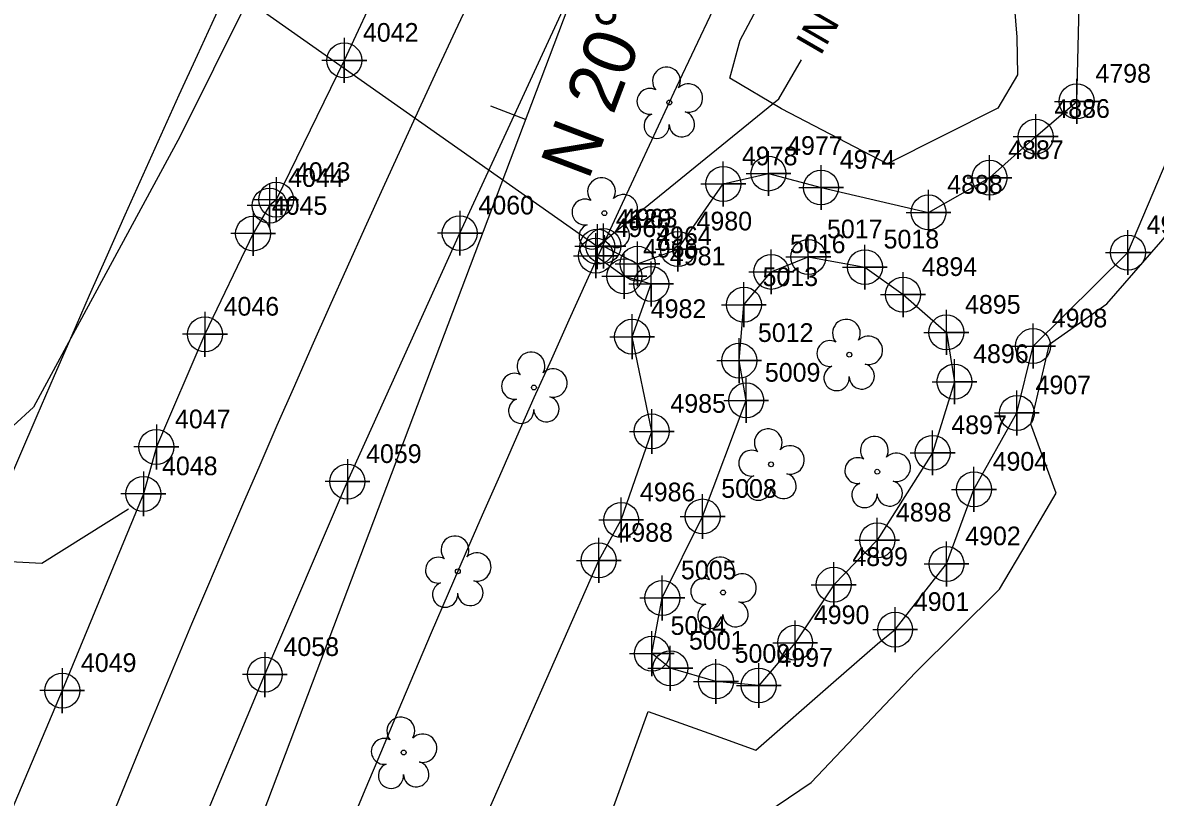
# Model space of a CAD drawing. Extents: x 1653123 to 1656194, y 596584 to 600233.
# Drawn here: x 1653582.5 to 1653734.2, y 597710.9 to 597814.6 of the extents above; entities that cross this region are included whole.
import ezdxf

# ---------------------------------------------------------------- set-up
doc = ezdxf.new("R2010")
doc.units = 0
for name, color, linetype in [('Exist Horizontal Alignment', 7, 'Continuous'), ('Exist Horizontal Baseline Alignment', 7, 'Continuous'), ('Exist Horizontal Baseline Alignment Direction Label', 7, 'Continuous'), ('Exist Horizontal Baseline Alignment Tick small', 7, 'Continuous'), ('Exist Hydro Jurisdictional Stream or Body of Water', 7, 'Continuous'), ('Exist Hydro Stream or Body of Water Cogo Number', 7, 'Continuous'), ('Exist Right of Way Line', 7, 'Continuous'), ('Exist Roads EOP Cogo Point CELL', 7, 'Continuous'), ('Exist Structure Minor Pipes RCP 30 Inch', 7, 'Continuous'), ('Exist Structure Minor Pipes RCP 30 Inch Cogo Number', 7, 'Continuous'), ('Exist Structure Minor Pipes RCP 30 Inch Cogo Point CELL', 7, 'Continuous'), ('Exist Structure Minor Pipes RCP 30 Inch Invert', 7, 'Continuous'), ('Exist Vegetation Tree CELL', 7, 'Continuous'), ('Exist Vegetation Woods Line', 7, 'Continuous'), ('Prop Conc Shoulder Berm Gutter', 7, 'Continuous'), ('Prop Easement Construction', 7, 'Continuous'), ('Prop Easement Construction Station Offsets', 7, 'Continuous'), ('Prop Guardrail Anchor Unit CELL', 7, 'Continuous'), ('Prop Horizontal Alignment', 7, 'Continuous')]:
    doc.layers.add(name, color=color, linetype=linetype)

msp = doc.modelspace()

# ---------------------------------------------------------------- linework, layer by layer
at = {"layer": 'Exist Horizontal Alignment'}
msp.add_arc((1655696.35, 596851.16), 2270, 149.9451, 159.30371, dxfattribs=at)
at = {"layer": 'Exist Horizontal Baseline Alignment'}
msp.add_line((1653570.02, 597590.97), (1653732.12, 598018.79), dxfattribs=at)
at = {"layer": 'Exist Horizontal Baseline Alignment Tick small'}
msp.add_line((1653649.85, 597801.66), (1653645.18, 597803.44), dxfattribs=at)
at = {"layer": 'Exist Hydro Jurisdictional Stream or Body of Water'}
for points in [[(1653703.81, 597789.23), (1653711.98, 597793.87), (1653718.16, 597799.38), (1653723.66, 597804.09), (1653724.22, 597826.08), (1653730.43, 597843.27), (1653737.9, 597848.38), (1653749, 597867.92), (1653762.46, 597888.24), (1653771.7, 597908), (1653776.11, 597927.83), (1653775.18, 597952.39), (1653772.63, 597974.68), (1653768.36, 597994.45), (1653761.04, 598003.47), (1653757.33, 598006.27), (1653756.65, 598007.49)], [(1653717.81, 597771.34), (1653730.52, 597783.85), (1653737.92, 597801.32)], [(1653670.24, 597784.32), (1653676.32, 597793.03), (1653682.37, 597794.43), (1653689.42, 597792.56), (1653703.81, 597789.23)], [(1653659.44, 597784.65), (1653659.25, 597783.43), (1653663.06, 597780.68), (1653666.67, 597779.65)], [(1653659.44, 597784.65), (1653660.26, 597784.72), (1653664.84, 597782.35), (1653670.24, 597784.32)], [(1653666.76, 597730.18), (1653668.15, 597737.62), (1653673.55, 597748.53), (1653679.39, 597764.07), (1653678.46, 597769.39), (1653679.08, 597776.87), (1653682.75, 597781.27), (1653687.71, 597783.27), (1653695.29, 597781.9), (1653700.39, 597778.22), (1653706.2, 597773.17)], [(1653638.42, 597694.46), (1653659.64, 597742.65), (1653662.65, 597748.06), (1653666.74, 597759.91), (1653664.11, 597772.59), (1653666.67, 597779.65)], [(1653693.8, 597570.3), (1653681.46, 597588.06), (1653671.05, 597605.1), (1653663.13, 597623.2), (1653653.04, 597647.87), (1653652.69, 597665.53), (1653656.24, 597688.24), (1653658.32, 597700.51), (1653666.26, 597722.43)]]:
    msp.add_lwpolyline(points, dxfattribs=at)
at = {"layer": 'Exist Right of Way Line'}
for radius in [2300, 2240]:
    msp.add_arc((1655696.35, 596851.16), radius, 149.9451, 159.30371, dxfattribs=at)
at = {"layer": 'Exist Roads EOP Cogo Point CELL'}
for points in [[(1653625.56, 597812.57), (1653625.56, 597806.57), (1653625.56, 597809.57), (1653628.56, 597809.57), (1653622.56, 597809.57)], [(1653615.55, 597793.14), (1653615.55, 597787.14), (1653615.55, 597790.14), (1653618.55, 597790.14), (1653612.55, 597790.14)], [(1653616.44, 597793.93), (1653616.44, 597787.93), (1653616.44, 597790.93), (1653619.44, 597790.93), (1653613.44, 597790.93)], [(1653613.35, 597789.4), (1653613.35, 597783.4), (1653613.35, 597786.4), (1653616.35, 597786.4), (1653610.35, 597786.4)], [(1653641.03, 597789.45), (1653641.03, 597783.45), (1653641.03, 597786.45), (1653644.03, 597786.45), (1653638.03, 597786.45)], [(1653606.9, 597775.91), (1653606.9, 597769.91), (1653606.9, 597772.91), (1653609.9, 597772.91), (1653603.9, 597772.91)], [(1653600.39, 597760.83), (1653600.39, 597754.83), (1653600.39, 597757.83), (1653603.39, 597757.83), (1653597.39, 597757.83)], [(1653625.98, 597756.19), (1653625.98, 597750.19), (1653625.98, 597753.19), (1653628.98, 597753.19), (1653622.98, 597753.19)], [(1653598.65, 597754.55), (1653598.65, 597748.55), (1653598.65, 597751.55), (1653601.65, 597751.55), (1653595.65, 597751.55)], [(1653614.92, 597730.36), (1653614.92, 597724.36), (1653614.92, 597727.36), (1653617.92, 597727.36), (1653611.92, 597727.36)], [(1653587.79, 597728.22), (1653587.79, 597722.22), (1653587.79, 597725.22), (1653590.79, 597725.22), (1653584.79, 597725.22)]]:
    msp.add_lwpolyline(points, dxfattribs=at)
for centre in [(1653625.56, 597809.57), (1653616.44, 597790.93), (1653615.55, 597790.14), (1653613.35, 597786.4), (1653641.03, 597786.45), (1653606.9, 597772.91), (1653600.39, 597757.83), (1653625.98, 597753.19), (1653598.65, 597751.55), (1653614.92, 597727.36), (1653587.79, 597725.22)]:
    msp.add_circle(centre, 2.34, dxfattribs=at)
at = {"layer": 'Exist Structure Minor Pipes RCP 30 Inch'}
msp.add_line((1653659.44, 597784.65), (1653609.16, 597820.02), dxfattribs=at)
at = {"layer": 'Exist Structure Minor Pipes RCP 30 Inch Cogo Point CELL'}
msp.add_lwpolyline([(1653659.44, 597787.65), (1653659.44, 597781.65), (1653659.44, 597784.65), (1653662.44, 597784.65), (1653656.44, 597784.65)], dxfattribs=at)
msp.add_circle((1653659.44, 597784.65), 2.34, dxfattribs=at)
at = {"layer": 'Exist Structure Minor Pipes RCP 30 Inch Invert'}
msp.add_lwpolyline([(1653659.44, 597784.65), (1653683.77, 597804.44), (1653686.78, 597809.63)], dxfattribs=at)
at = {"layer": 'Exist Vegetation Tree CELL'}
for p, q in [((1653669.1, 597803.94), (1653669.1, 597803.94)), ((1653660.4, 597789.12), (1653660.4, 597789.12)), ((1653693.2, 597770.18), (1653693.2, 597770.18)), ((1653650.96, 597765.8), (1653650.96, 597765.8)), ((1653682.72, 597755.51), (1653682.72, 597755.51)), ((1653696.94, 597754.52), (1653696.94, 597754.52)), ((1653640.77, 597741.19), (1653640.77, 597741.19)), ((1653676.29, 597738.36), (1653676.29, 597738.36)), ((1653633.51, 597716.94), (1653633.51, 597716.94))]:
    msp.add_line(p, q, dxfattribs=at)
for centre in [(1653669.1, 597803.94), (1653660.4, 597789.12), (1653693.2, 597770.18), (1653650.96, 597765.8), (1653682.72, 597755.51), (1653696.94, 597754.52), (1653640.77, 597741.19), (1653676.29, 597738.36), (1653633.51, 597716.94)]:
    msp.add_circle(centre, 0.326, dxfattribs=at)
for centre, radius, start, end in [((1653668.71, 597806.81), 1.86, 330.1651, 219.7134), ((1653666.49, 597804.09), 1.73, 62.6636, 279.3457), ((1653671.65, 597804.53), 1.9, 257.1011, 134.1999), ((1653667.39, 597800.82), 1.69, 111.5671, 6.231), ((1653670.77, 597801.04), 1.7, 181.2822, 74.56), ((1653660.01, 597792), 1.86, 330.1651, 219.7134), ((1653662.95, 597789.71), 1.9, 257.1011, 134.1999), ((1653657.79, 597789.28), 1.73, 62.6636, 279.3457), ((1653658.69, 597786), 1.69, 111.5671, 6.231), ((1653662.07, 597786.23), 1.7, 181.2822, 74.56), ((1653692.81, 597773.06), 1.86, 330.1651, 219.7134), ((1653690.59, 597770.34), 1.73, 62.6636, 279.3457), ((1653695.75, 597770.77), 1.9, 257.1011, 134.1999), ((1653650.57, 597768.68), 1.86, 330.1651, 219.7134), ((1653694.87, 597767.28), 1.7, 181.2822, 74.56), ((1653648.35, 597765.96), 1.73, 62.6636, 279.3457), ((1653653.51, 597766.39), 1.9, 257.1011, 134.1999), ((1653691.49, 597767.06), 1.69, 111.5671, 6.231), ((1653649.25, 597762.68), 1.69, 111.5671, 6.231), ((1653652.63, 597762.9), 1.7, 181.2822, 74.56), ((1653682.34, 597758.39), 1.86, 330.1651, 219.7134), ((1653696.55, 597757.39), 1.86, 330.1651, 219.7134), ((1653680.12, 597755.67), 1.73, 62.6636, 279.3457), ((1653685.27, 597756.1), 1.9, 257.1011, 134.1999), ((1653699.49, 597755.11), 1.9, 257.1011, 134.1999), ((1653694.33, 597754.67), 1.73, 62.6636, 279.3457), ((1653681.02, 597752.39), 1.69, 111.5671, 6.231), ((1653684.39, 597752.62), 1.7, 181.2822, 74.56), ((1653695.23, 597751.4), 1.69, 111.5671, 6.231), ((1653698.61, 597751.62), 1.7, 181.2822, 74.56), ((1653640.39, 597744.06), 1.86, 330.1651, 219.7134), ((1653638.17, 597741.34), 1.73, 62.6636, 279.3457), ((1653643.32, 597741.77), 1.9, 257.1011, 134.1999), ((1653675.91, 597741.23), 1.86, 330.1651, 219.7134), ((1653673.69, 597738.51), 1.73, 62.6636, 279.3457), ((1653678.84, 597738.95), 1.9, 257.1011, 134.1999), ((1653639.07, 597738.07), 1.69, 111.5671, 6.231), ((1653642.44, 597738.29), 1.7, 181.2822, 74.56), ((1653677.96, 597735.46), 1.7, 181.2822, 74.56), ((1653674.59, 597735.24), 1.69, 111.5671, 6.231), ((1653633.13, 597719.81), 1.86, 330.1651, 219.7134), ((1653630.91, 597717.09), 1.73, 62.6636, 279.3457), ((1653636.06, 597717.52), 1.9, 257.1011, 134.1999), ((1653631.81, 597713.82), 1.69, 111.5671, 6.231), ((1653635.19, 597714.04), 1.7, 181.2822, 74.56)]:
    msp.add_arc(centre, radius, start, end, dxfattribs=at)
at = {"layer": 'Exist Vegetation Woods Line'}
for points in [[(1653661.33, 597915.51), (1653603.59, 597799.41), (1653583.95, 597763.16), (1653578.44, 597758.17), (1653564.7, 597761.25), (1653536.01, 597770.5), (1653508.63, 597776.57), (1653484.83, 597779.68), (1653482.87, 597781.33), (1653483.43, 597790.56), (1653492.03, 597811.3), (1653503.66, 597836.47), (1653511.56, 597849.92), (1653513.67, 597858.14), (1653513.6, 597868.54), (1653511.35, 597878.91), (1653507.78, 597891.42), (1653504.66, 597919.45), (1653504.85, 597944.49), (1653506.49, 597968.64), (1653509.77, 597999.99)], [(1653743.53, 597872.59), (1653727.72, 597849.07), (1653722.44, 597840.57), (1653717.66, 597833.58), (1653714.51, 597826.4), (1653715.63, 597812.68), (1653715.73, 597807.63), (1653713.11, 597803.16), (1653698.27, 597795.72), (1653684.13, 597803.11), (1653677.18, 597807.18), (1653678.58, 597812.27), (1653717.51, 597885.35)], [(1653682.04, 597708.83), (1653688.1, 597712.91), (1653702.08, 597727.65), (1653713.33, 597738.79), (1653717.03, 597745.05), (1653720.88, 597751.65), (1653717.53, 597760.89), (1653720.03, 597771.59), (1653727.67, 597777.01), (1653736.11, 597786.67), (1653742.22, 597795.29), (1653745.11, 597800.08), (1653748.1, 597805.18), (1653747.38, 597813.21), (1653742.97, 597818.93), (1653743.36, 597824.69), (1653753.29, 597833.05), (1653760.6, 597841.3), (1653772.69, 597855.66)]]:
    msp.add_lwpolyline(points, dxfattribs=at)
at = {"layer": 'Prop Conc Shoulder Berm Gutter'}
for points in [[(1653736.93, 598020.21), (1653736.61, 598019), (1653719.2, 597989.18), (1653700.61, 597956.07), (1653684.64, 597926.74), (1653670.3, 597899.63), (1653655.34, 597870.98), (1653640.41, 597841.45), (1653625.56, 597809.57), (1653616.44, 597790.93), (1653615.55, 597790.14), (1653613.35, 597786.4), (1653606.9, 597772.91), (1653600.39, 597757.83), (1653598.65, 597751.55), (1653587.79, 597725.22), (1653577.73, 597701.58), (1653574.75, 597692.21), (1653558.96, 597651.01), (1653542.08, 597605.71)], [(1653564.52, 597597.65), (1653581.19, 597642.12), (1653595.32, 597679.04), (1653605.24, 597704.17), (1653614.92, 597727.36), (1653625.98, 597753.19), (1653641.03, 597786.45), (1653655.92, 597818.68), (1653671.74, 597850.93), (1653688.35, 597883.45), (1653707.13, 597918.97), (1653720.66, 597943.73), (1653734.86, 597970.07), (1653749.84, 597996.36), (1653750.81, 597997.29)]]:
    msp.add_lwpolyline(points, dxfattribs=at)
at = {"layer": 'Prop Easement Construction'}
msp.add_lwpolyline([(1653468.85, 597775.82), (1653471.26, 597768.82), (1653474.67, 597765.31), (1653499.27, 597762.1), (1653508.84, 597760.94), (1653515.47, 597759.8), (1653528.77, 597757.03), (1653546.84, 597752.13), (1653557.14, 597748.35), (1653573.98, 597742.86), (1653585.04, 597742.26), (1653596.67, 597749.54)], dxfattribs=at)
at = {"layer": 'Prop Easement Construction Station Offsets'}
for points in [[(1653706.2, 597773.17), (1653707.28, 597766.57), (1653704.36, 597757.05), (1653696.94, 597745.35), (1653691.11, 597739.4), (1653685.95, 597731.63), (1653681.07, 597725.91), (1653675.34, 597726.45), (1653669.22, 597728.21), (1653666.76, 597730.18)], [(1653699.34, 597733.39), (1653706.22, 597742.18), (1653709.89, 597752.16), (1653715.64, 597762.39), (1653717.81, 597771.34)], [(1653666.26, 597722.43), (1653674.4, 597719.52), (1653680.68, 597717.27), (1653691.06, 597726.37), (1653696.97, 597731.5), (1653699.34, 597733.39)]]:
    msp.add_lwpolyline(points, dxfattribs=at)
at = {"layer": 'Prop Guardrail Anchor Unit CELL'}
for points in [[(1653720.66, 597804.09), (1653726.66, 597804.09), (1653723.66, 597804.09), (1653723.66, 597801.09), (1653723.66, 597807.09)], [(1653715.16, 597799.38), (1653721.16, 597799.38), (1653718.16, 597799.38), (1653718.16, 597796.38), (1653718.16, 597802.38)], [(1653679.37, 597794.43), (1653685.37, 597794.43), (1653682.37, 597794.43), (1653682.37, 597791.43), (1653682.37, 597797.43)], [(1653708.98, 597793.87), (1653714.98, 597793.87), (1653711.98, 597793.87), (1653711.98, 597790.87), (1653711.98, 597796.87)], [(1653673.32, 597793.03), (1653679.32, 597793.03), (1653676.32, 597793.03), (1653676.32, 597790.03), (1653676.32, 597796.03)], [(1653686.42, 597792.56), (1653692.42, 597792.56), (1653689.42, 597792.56), (1653689.42, 597789.56), (1653689.42, 597795.56)], [(1653700.81, 597789.23), (1653706.81, 597789.23), (1653703.81, 597789.23), (1653703.81, 597786.23), (1653703.81, 597792.23)], [(1653657.26, 597784.72), (1653663.26, 597784.72), (1653660.26, 597784.72), (1653660.26, 597781.72), (1653660.26, 597787.72)], [(1653667.24, 597784.32), (1653673.24, 597784.32), (1653670.24, 597784.32), (1653670.24, 597781.32), (1653670.24, 597787.32)], [(1653656.25, 597783.43), (1653662.25, 597783.43), (1653659.25, 597783.43), (1653659.25, 597780.43), (1653659.25, 597786.43)], [(1653684.71, 597783.27), (1653690.71, 597783.27), (1653687.71, 597783.27), (1653687.71, 597780.27), (1653687.71, 597786.27)], [(1653727.52, 597783.85), (1653733.52, 597783.85), (1653730.52, 597783.85), (1653730.52, 597780.85), (1653730.52, 597786.85)], [(1653661.84, 597782.35), (1653667.84, 597782.35), (1653664.84, 597782.35), (1653664.84, 597779.35), (1653664.84, 597785.35)], [(1653679.75, 597781.27), (1653685.75, 597781.27), (1653682.75, 597781.27), (1653682.75, 597778.27), (1653682.75, 597784.27)], [(1653692.29, 597781.9), (1653698.29, 597781.9), (1653695.29, 597781.9), (1653695.29, 597778.9), (1653695.29, 597784.9)], [(1653660.06, 597780.68), (1653666.06, 597780.68), (1653663.06, 597780.68), (1653663.06, 597777.68), (1653663.06, 597783.68)], [(1653663.67, 597779.65), (1653669.67, 597779.65), (1653666.67, 597779.65), (1653666.67, 597776.65), (1653666.67, 597782.65)], [(1653697.39, 597778.22), (1653703.39, 597778.22), (1653700.39, 597778.22), (1653700.39, 597775.22), (1653700.39, 597781.22)], [(1653676.08, 597776.87), (1653682.08, 597776.87), (1653679.08, 597776.87), (1653679.08, 597773.87), (1653679.08, 597779.87)], [(1653661.11, 597772.59), (1653667.11, 597772.59), (1653664.11, 597772.59), (1653664.11, 597769.59), (1653664.11, 597775.59)], [(1653703.2, 597773.17), (1653709.2, 597773.17), (1653706.2, 597773.17), (1653706.2, 597770.17), (1653706.2, 597776.17)], [(1653714.81, 597771.34), (1653720.81, 597771.34), (1653717.81, 597771.34), (1653717.81, 597768.34), (1653717.81, 597774.34)], [(1653675.46, 597769.39), (1653681.46, 597769.39), (1653678.46, 597769.39), (1653678.46, 597766.39), (1653678.46, 597772.39)], [(1653704.28, 597766.57), (1653710.28, 597766.57), (1653707.28, 597766.57), (1653707.28, 597763.57), (1653707.28, 597769.57)], [(1653676.39, 597764.07), (1653682.39, 597764.07), (1653679.39, 597764.07), (1653679.39, 597761.07), (1653679.39, 597767.07)], [(1653712.64, 597762.39), (1653718.64, 597762.39), (1653715.64, 597762.39), (1653715.64, 597759.39), (1653715.64, 597765.39)], [(1653663.74, 597759.91), (1653669.74, 597759.91), (1653666.74, 597759.91), (1653666.74, 597756.91), (1653666.74, 597762.91)], [(1653701.36, 597757.05), (1653707.36, 597757.05), (1653704.36, 597757.05), (1653704.36, 597754.05), (1653704.36, 597760.05)], [(1653706.89, 597752.16), (1653712.89, 597752.16), (1653709.89, 597752.16), (1653709.89, 597749.16), (1653709.89, 597755.16)], [(1653659.65, 597748.06), (1653665.65, 597748.06), (1653662.65, 597748.06), (1653662.65, 597745.06), (1653662.65, 597751.06)], [(1653670.55, 597748.53), (1653676.55, 597748.53), (1653673.55, 597748.53), (1653673.55, 597745.53), (1653673.55, 597751.53)], [(1653693.94, 597745.35), (1653699.94, 597745.35), (1653696.94, 597745.35), (1653696.94, 597742.35), (1653696.94, 597748.35)], [(1653656.64, 597742.65), (1653662.64, 597742.65), (1653659.64, 597742.65), (1653659.64, 597739.65), (1653659.64, 597745.65)], [(1653703.22, 597742.18), (1653709.22, 597742.18), (1653706.22, 597742.18), (1653706.22, 597739.18), (1653706.22, 597745.18)], [(1653688.11, 597739.4), (1653694.11, 597739.4), (1653691.11, 597739.4), (1653691.11, 597736.4), (1653691.11, 597742.4)], [(1653665.15, 597737.62), (1653671.15, 597737.62), (1653668.15, 597737.62), (1653668.15, 597734.62), (1653668.15, 597740.62)], [(1653696.34, 597733.39), (1653702.34, 597733.39), (1653699.34, 597733.39), (1653699.34, 597730.39), (1653699.34, 597736.39)], [(1653682.95, 597731.63), (1653688.95, 597731.63), (1653685.95, 597731.63), (1653685.95, 597728.63), (1653685.95, 597734.63)], [(1653663.76, 597730.18), (1653669.76, 597730.18), (1653666.76, 597730.18), (1653666.76, 597727.18), (1653666.76, 597733.18)], [(1653666.22, 597728.21), (1653672.22, 597728.21), (1653669.22, 597728.21), (1653669.22, 597725.21), (1653669.22, 597731.21)], [(1653672.34, 597726.45), (1653678.34, 597726.45), (1653675.34, 597726.45), (1653675.34, 597723.45), (1653675.34, 597729.45)], [(1653678.07, 597725.91), (1653684.07, 597725.91), (1653681.07, 597725.91), (1653681.07, 597722.91), (1653681.07, 597728.91)]]:
    msp.add_lwpolyline(points, dxfattribs=at)
for centre in [(1653723.66, 597804.09), (1653718.16, 597799.38), (1653682.37, 597794.43), (1653711.98, 597793.87), (1653676.32, 597793.03), (1653689.42, 597792.56), (1653703.81, 597789.23), (1653660.26, 597784.72), (1653659.25, 597783.43), (1653670.24, 597784.32), (1653687.71, 597783.27), (1653730.52, 597783.85), (1653664.84, 597782.35), (1653695.29, 597781.9), (1653663.06, 597780.68), (1653682.75, 597781.27), (1653666.67, 597779.65), (1653700.39, 597778.22), (1653679.08, 597776.87), (1653664.11, 597772.59), (1653706.2, 597773.17), (1653717.81, 597771.34), (1653678.46, 597769.39), (1653707.28, 597766.57), (1653679.39, 597764.07), (1653715.64, 597762.39), (1653666.74, 597759.91), (1653704.36, 597757.05), (1653709.89, 597752.16), (1653673.55, 597748.53), (1653662.65, 597748.06), (1653696.94, 597745.35), (1653659.64, 597742.65), (1653706.22, 597742.18), (1653691.11, 597739.4), (1653668.15, 597737.62), (1653699.34, 597733.39), (1653685.95, 597731.63), (1653666.76, 597730.18), (1653669.22, 597728.21), (1653675.34, 597726.45), (1653681.07, 597725.91)]:
    msp.add_circle(centre, 2.34, dxfattribs=at)

# ---------------------------------------------------------------- texts
at = {"layer": 'Exist Horizontal Baseline Alignment Direction Label'}
msp.add_text('N 20%%d 45\' 05.5" E', height=7, rotation=69.2485, dxfattribs=at).set_placement((1653658.25, 597793.4))
at = {"layer": 'Exist Hydro Stream or Body of Water Cogo Number'}
for s, p in [('4798', (1653726.16, 597806.59)), ('4886', (1653720.66, 597801.88)), ('4977', (1653684.87, 597796.93)), ('4978', (1653678.82, 597795.53)), ('4887', (1653714.48, 597796.37)), ('4974', (1653691.92, 597795.06)), ('4888', (1653706.31, 597791.73)), ('4963', (1653662.76, 597787.22)), ('4980', (1653672.74, 597786.82)), ('4909', (1653733.02, 597786.35)), ('4965', (1653661.75, 597785.93)), ('4964', (1653667.34, 597784.85)), ('5017', (1653690.21, 597785.77)), ('4966', (1653665.56, 597783.18)), ('5016', (1653685.25, 597783.77)), ('5018', (1653697.79, 597784.4)), ('4981', (1653669.17, 597782.15)), ('4894', (1653702.89, 597780.72)), ('5013', (1653681.58, 597779.37)), ('4895', (1653708.7, 597775.67)), ('4982', (1653666.61, 597775.09)), ('4908', (1653720.31, 597773.84)), ('5012', (1653680.96, 597771.89)), ('4896', (1653709.78, 597769.07)), ('5009', (1653681.89, 597766.57)), ('4907', (1653718.14, 597764.89)), ('4985', (1653669.24, 597762.41)), ('4897', (1653706.86, 597759.55)), ('4904', (1653712.39, 597754.66)), ('4986', (1653665.15, 597750.56)), ('5008', (1653676.05, 597751.03)), ('4898', (1653699.44, 597747.85)), ('4988', (1653662.14, 597745.15)), ('4902', (1653708.72, 597744.68)), ('4899', (1653693.61, 597741.9)), ('5005', (1653670.65, 597740.12)), ('4901', (1653701.84, 597735.89)), ('4990', (1653688.45, 597734.13)), ('5004', (1653669.26, 597732.68)), ('5001', (1653671.72, 597730.71)), ('5000', (1653677.84, 597728.95)), ('4997', (1653683.57, 597728.41))]:
    msp.add_text(s, height=2.5, dxfattribs=at).set_placement(p)
at = {"layer": 'Exist Structure Minor Pipes RCP 30 Inch Cogo Number'}
msp.add_text('4129', height=2.5, dxfattribs=at).set_placement((1653661.94, 597787.15))
at = {"layer": 'Exist Structure Minor Pipes RCP 30 Inch Invert'}
msp.add_text("INV=535.31'", height=4, rotation=59.9255, dxfattribs=at).set_placement((1653689.32, 597810.06))
at = {"layer": 'Prop Horizontal Alignment'}
for s, p in [('4042', (1653628.06, 597812.07)), ('4044', (1653618.05, 597792.64)), ('4043', (1653618.94, 597793.43)), ('4045', (1653615.85, 597788.9)), ('4060', (1653643.53, 597788.95)), ('4046', (1653609.4, 597775.41)), ('4047', (1653602.89, 597760.33)), ('4059', (1653628.48, 597755.69)), ('4048', (1653601.15, 597754.05)), ('4058', (1653617.42, 597729.86)), ('4049', (1653590.29, 597727.72))]:
    msp.add_text(s, height=2.5, dxfattribs=at).set_placement(p)

doc.saveas('drawing.dxf')
